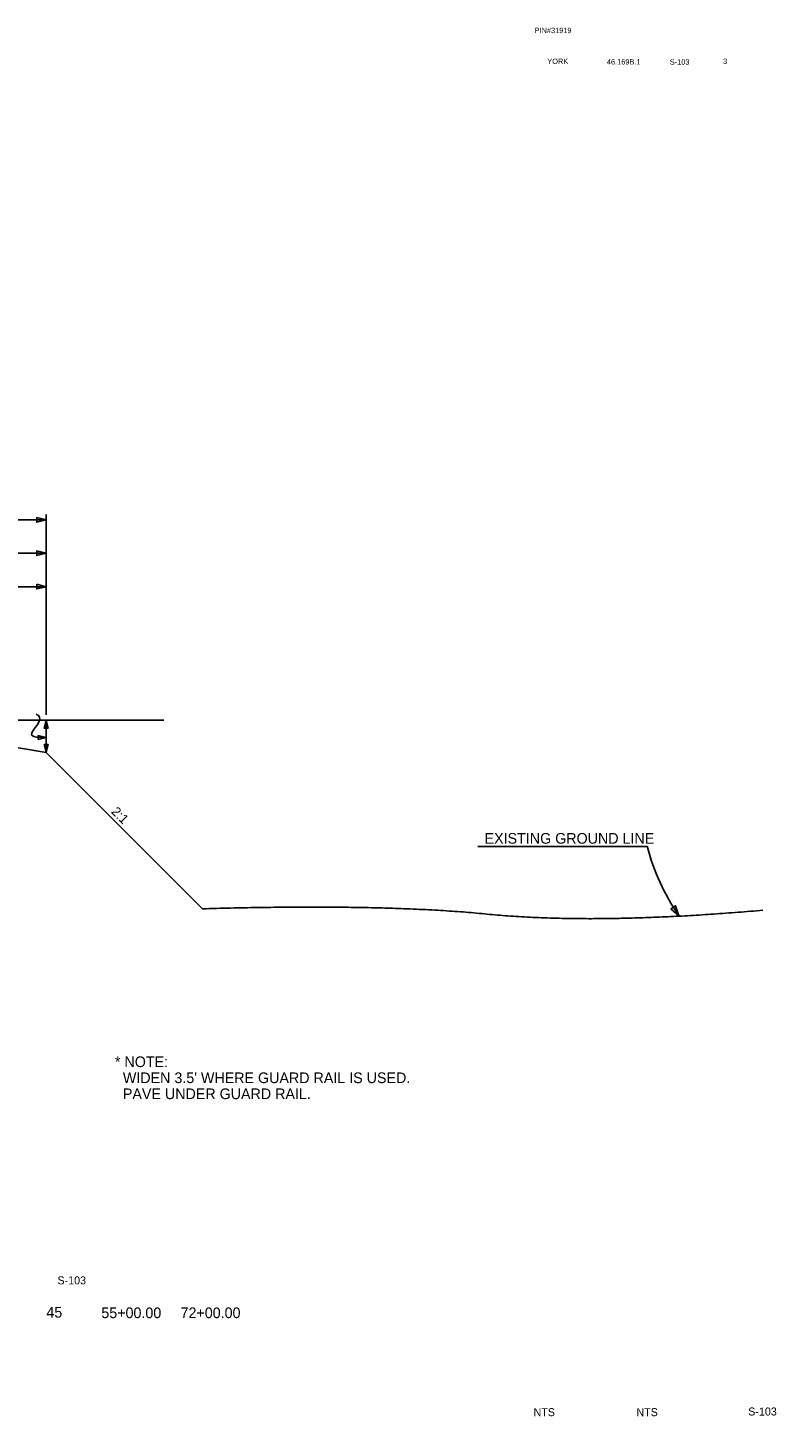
# Model space of a CAD drawing. Extents: x -859 to 797, y 1810 to 2851.
# Drawn here: x 236 to 797, y 1810 to 2851 of the extents above; entities that cross this region are included whole.
import ezdxf

# ---------------------------------------------------------------- set-up
doc = ezdxf.new("R2010")
doc.units = 0
doc.layers.add('Level 41', color=7, linetype='Continuous')

msp = doc.modelspace()

# ---------------------------------------------------------------- linework, layer by layer
at = {"layer": 'Level 41'}
for p, q in [((-33.3, 2481.7), (250, 2481.7)), ((250, 2335.7), (250, 2485.7)), ((250, 2456.7), (150, 2456.7)), ((250, 2335.7), (250, 2460.7)), ((183.4, 2431.7), (250, 2431.7)), ((-554.3, 2331.7), (338.2, 2331.7)), ((250, 2307.4), (250, 2331.7)), ((183.4, 2318.5), (250, 2307.4)), ((250, 2307.4), (367.3, 2190.2)), ((700.5, 2237), (573.7, 2237))]:
    msp.add_line(p, q, dxfattribs=at)
for points in [[(243, 2483.5), (250, 2481.7), (243, 2480)], [(243, 2458.5), (250, 2456.7), (243, 2455)], [(243, 2455), (250, 2456.7), (243, 2458.5)], [(243, 2433.5), (250, 2431.7), (243, 2430)], [(251.5, 2325.7), (250, 2331.7), (248.5, 2325.7)], [(244, 2317), (250, 2318.5), (244, 2320)], [(248.5, 2313.4), (250, 2307.4), (251.5, 2313.4)], [(718.3, 2190.1), (724.4, 2184.9), (721.7, 2192.5)]]:
    msp.add_lwpolyline(points, close=True, dxfattribs=at)
msp.add_arc((862.2, 2279.7), 167.2, 194.7854, 214.5255, dxfattribs=at)
for points, degree in [([(250, 2318.5), (237.3, 2318.4), (238.7, 2323), (248.4, 2333.7), (242.5, 2336.2)], 3), ([(367.3, 2190.2), (501.3, 2194.1), (661.5, 2178.2), (787.3, 2189.1)], 2)]:
    msp.add_open_spline(points, degree=degree, dxfattribs=at)

# ---------------------------------------------------------------- texts
for s, height, p in [('PIN#31919', 4, (616.2, 2846.7)), ('YORK', 4, (625.7, 2823.6)), ('46.169B.1', 4, (670.4, 2823.2)), ('S-103', 4, (717.5, 2823.1)), ('3', 4, (757.5, 2823.6)), ('EXISTING GROUND LINE', 8, (578.7, 2239)), ('* NOTE:', 8, (301.6, 2071.5)), ("  WIDEN 3.5' WHERE GUARD RAIL IS USED.", 8, (301.6, 2059.5)), ('  PAVE UNDER GUARD RAIL.', 8, (301.6, 2047.5)), ('S-103', 6, (258.5, 1908.6)), ('45', 8, (250.2, 1883.7)), ('55+00.00', 8, (291.4, 1883.3)), ('72+00.00', 8, (350.8, 1883.3)), ('NTS', 6, (615.4, 1809.8)), ('NTS', 6, (692.5, 1809.8)), ('S-103', 6, (776.3, 1810.3))]:
    msp.add_text(s, height=height, dxfattribs=at).set_placement(p)
msp.add_text('2:1', height=7, rotation=315, dxfattribs=at).set_placement((298.4, 2262.5))

doc.saveas('drawing.dxf')
